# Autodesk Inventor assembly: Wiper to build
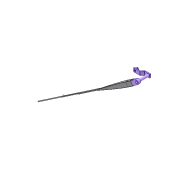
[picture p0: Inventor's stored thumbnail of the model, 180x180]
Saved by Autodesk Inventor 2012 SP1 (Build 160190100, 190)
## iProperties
Created: 2006-03
Part Number: Wiper to build
Document SubType Name: Assembly
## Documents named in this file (6)
- D:\Backup\Autodesk Motion Files\Inv2012DynSim\Sub-Assemblies\Complete_wiper_right_asm.iam
- D:\Backup\Autodesk Motion Files\Inv2012DynSim\Parts\Axis_Right.ipt
- D:\Backup\Autodesk Motion Files\Inv2012DynSim\Parts\Support_Wiper.ipt
- D:\Backup\Autodesk Motion Files\Inv2012DynSim\Parts\Crank_right.ipt
- D:\Backup\Autodesk Motion Files\Inv2012DynSim\Parts\Pawn_2.ipt
- D:\Backup\Autodesk Motion Files\Inv2012DynSim\Sub-Assemblies\Brush_asm_right.iam
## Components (5 placed, 5 different names)
1. Axis_Right:1 — Mate:18, Flush:4, Angle:9, Mate:32, Mate:33, Mate:34
2. Support_Wiper:1 — Mate:18, Flush:4, Angle:9
3. Crank_right:1 — Mate:29, Mate:30, Mate:31, Mate:32, Mate:33, Mate:34, Mate:35, Mate:36, Angle:10, Angle:11
4. Pawn_2:1 — Mate:35, Mate:36, Mate:39, Flush:5
5. Brush_asm_right:1 [sub-assembly]
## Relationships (15: Mate 10, Angle 3, Flush 2)
- Mate:18: Axis_Right:1 ↔ Support_Wiper:1
- Flush:4: Axis_Right:1 ↔ Support_Wiper:1
- Angle:9: Axis_Right:1 ↔ Support_Wiper:1
- Mate:29: Crank_right:1
- Mate:30: Crank_right:1
- Mate:31: Crank_right:1
- Mate:32: Axis_Right:1 ↔ Crank_right:1
- Mate:33: Axis_Right:1 ↔ Crank_right:1
- Mate:34: Axis_Right:1 ↔ Crank_right:1
- Mate:35: Crank_right:1 ↔ Pawn_2:1
- Mate:36: Crank_right:1 ↔ Pawn_2:1
- Mate:39: Pawn_2:1
- Angle:10: Crank_right:1
- Flush:5: Pawn_2:1
- Angle:11: Crank_right:1
